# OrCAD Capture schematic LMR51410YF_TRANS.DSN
size D; title: LMR51410YF SIMPLE SWITCHERï¿½ 4.5-V to 42-V, 1000-mA; note: Datasheet: SLUSFL8     EVM: SLUUCO6; note: Synchronous Step-Down Converter
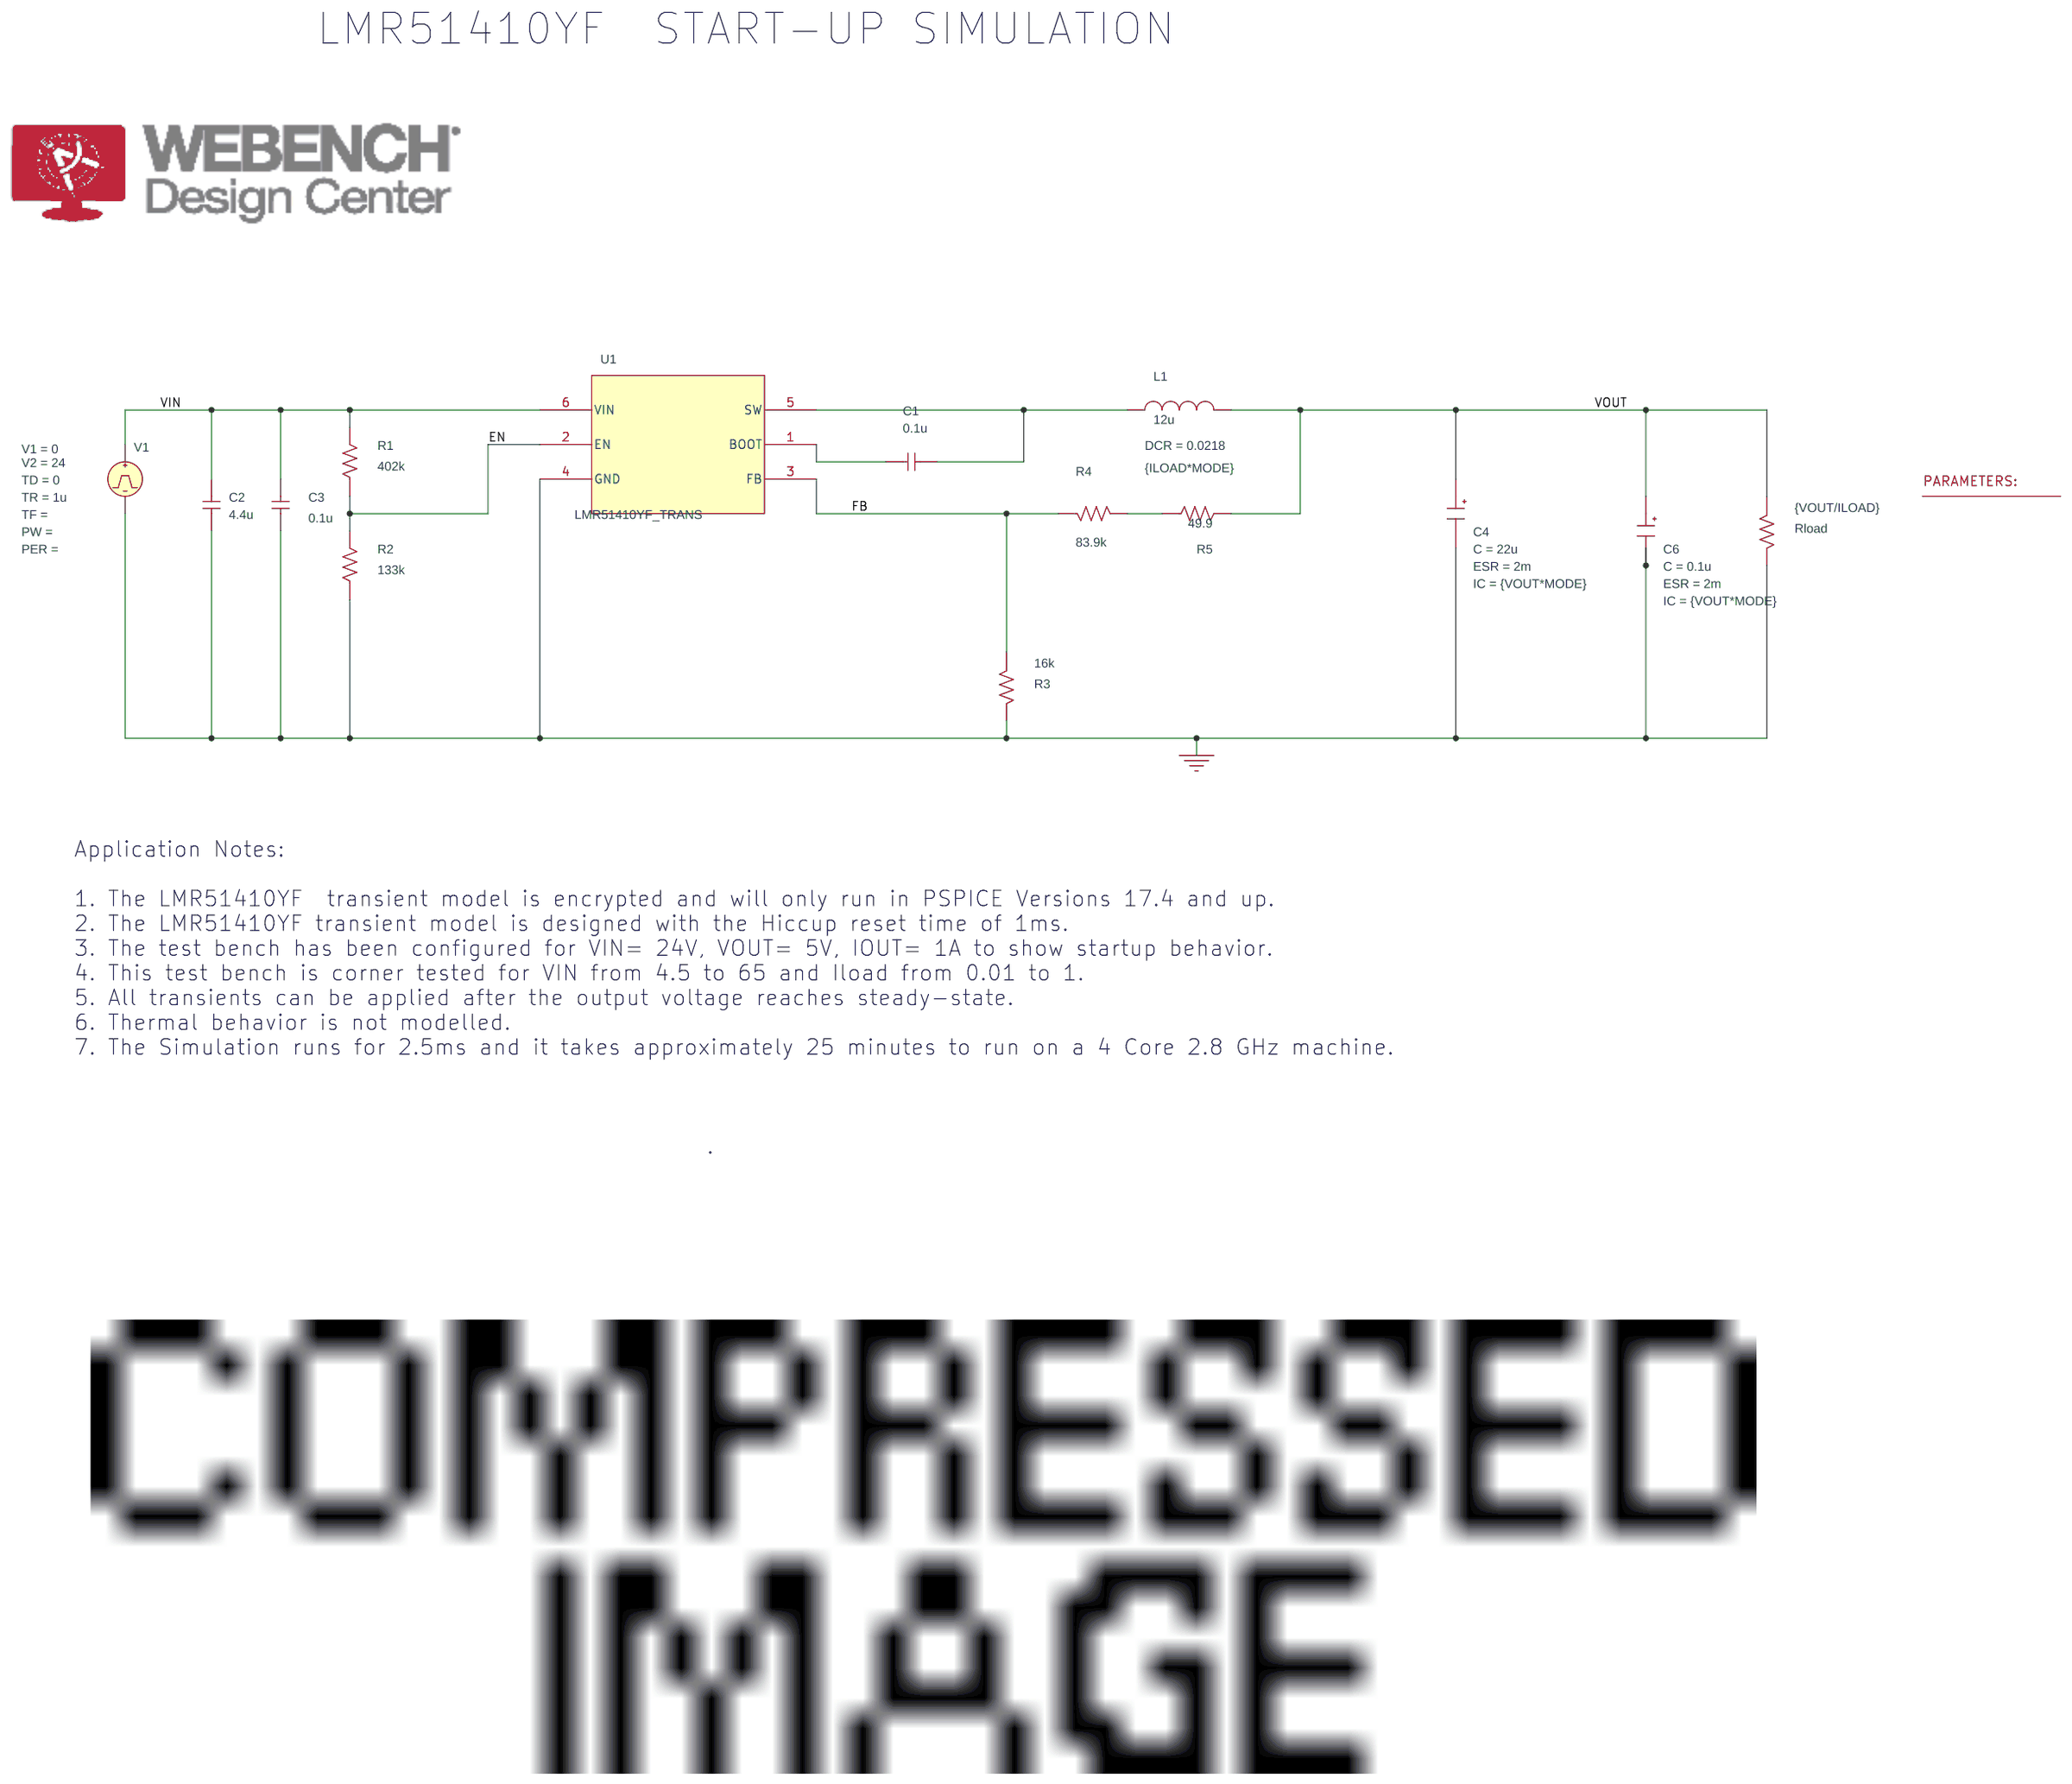
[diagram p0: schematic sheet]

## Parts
1  PARAM
C1  0.1u  [RAD/CK05]
C2  4.4u  [RAD/CK05]
C3  0.1u  [RAD/CK05]
C4  CESR
C6  CESR
L1  12u  [DISC/.350x.175/LS.200x.100/.034]
R1  402k  [AX/RC05]
R2  133k  [AX/RC05]
R3  16k  [AX/RC05]
R4  83.9k  [AX/RC05]
R5  49.9  [AX/RC05]
Rload  {VOUT/ILOAD}  [AX/RC05]
U1  LMR51410YF_TRANS
V1  VPULSE

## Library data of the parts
1 = PARAM: MODE: 0; VOUT: 5
C1 = C: IC: -3.3
C2 C3 = C
C4 = CESR_0: C: 22u; ESR: 2m; IC: {VOUT*MODE}; PSpiceTemplate: X^@REFDES %IN %OUT @MODEL PARAMS:  ?C|C=@C||C=100u|  ?ESR|ESR=@ESR||ESR=0.01| ?X|X=@X||X=2|  ?IC|IC=@IC||IC=2|; X: 1
C6 = CESR_0: C: 0.1u; ESR: 2m; IC: {VOUT*MODE}; PSpiceTemplate: X^@REFDES %IN %OUT @MODEL PARAMS:  ?C|C=@C||C=100u|  ?ESR|ESR=@ESR||ESR=0.01| ?X|X=@X||X=2|  ?IC|IC=@IC||IC=2|; X: 1
L1 = L: DCR: 0.0218; IC: {ILOAD*MODE}
R1 R2 R5 Rload = R
R3 R4 = r
U1 = LMR51410YF_TRANS
V1 = VPULSE: TD: 0; TR: 1u; V1: 0; V2: 24

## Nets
VIN: C2.2 C3.2 R1.2 U1.6(VIN) V1.1(+)
0: C2.1 C3.1 C4.3(OUT) C6.3(OUT) R2.1 R3.2 Rload.2 U1.4(GND) V1.2(-)
EN: R1.1 R2.2 U1.2(EN)
FB: R3.1 R4.1 U1.3(FB)
VOUT: C4.1(IN) C6.1(IN) L1.2 R5.2 Rload.1
N16764843: R4.2 R5.1
N16764891: C1.2 L1.1 U1.5(SW)
N16778061: C1.1 U1.1(BOOT)

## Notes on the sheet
- LMR51410YF  START-UP SIMULATION
- Application Notes:
  1. The LMR51410YF  transient model is encrypted and will only run in PSPICE Versions 17.4 and up.
  2. The LMR51410YF transient model is designed with the Hiccup reset time of 1ms.
  3. The test bench has been configured for VIN= 24V, VOUT= 5V, IOUT= 1A to show startup behavior.
  4. This test bench is corner tested for VIN from 4.5 to 65 and Iload from 0.01 to 1.
  5. All transients can be applied after the output voltage reaches steady-state.
  6. Thermal behavior is not modelled.
  7. The Simulation runs for 2.5ms and it takes approximately 25 minutes to run on a 4 Core 2.8 GHz machine.
                                                        .
